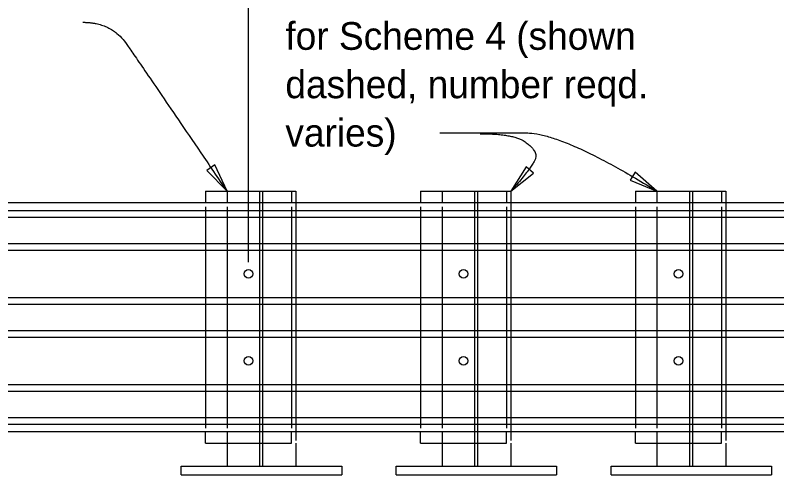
# Model space of a CAD drawing. Extents: x 21587 to 21656.3, y 56114 to 56157.2.
# Drawn here: x 21593.9 to 21599.43, y 56134.8 to 56138.14 of the extents above; entities that cross this region are included whole.
import ezdxf

# ---------------------------------------------------------------- set-up
doc = ezdxf.new("R2010")
doc.units = 0
for name, color, linetype in [('Border', 7, 'Continuous'), ('Patterning', 7, 'Continuous'), ('PlotBorder_dp', 7, 'Continuous'), ('TextMisc', 7, 'Continuous')]:
    doc.layers.add(name, color=color, linetype=linetype)

msp = doc.modelspace()

# ---------------------------------------------------------------- linework, layer by layer
at = {"layer": 'Border'}
for p, q in [((21595.4377, 56136.8635), (21595.9377, 56136.8635)), ((21595.4377, 56136.8635), (21595.4377, 56136.7802)), ((21599.7592, 56136.7801), (21587.6633, 56136.7801)), ((21587.6633, 56136.7246), (21599.7592, 56136.7246)), ((21587.6633, 56136.6764), (21599.7592, 56136.6764)), ((21587.6633, 56136.4835), (21599.7592, 56136.4835)), ((21587.6633, 56136.4353), (21599.7592, 56136.4353)), ((21587.6633, 56136.0914), (21599.7592, 56136.0914)), ((21587.6633, 56136.0431), (21599.7592, 56136.0431)), ((21587.6633, 56135.8503), (21599.7592, 56135.8503)), ((21587.6633, 56135.8022), (21599.7592, 56135.8022)), ((21587.6633, 56135.4582), (21599.7592, 56135.4582)), ((21587.6633, 56135.41), (21599.7592, 56135.41)), ((21587.6633, 56135.2172), (21599.7592, 56135.2172)), ((21587.6633, 56135.169), (21599.7592, 56135.169)), ((21599.7592, 56135.1134), (21587.6633, 56135.1134)), ((21595.4377, 56135.1135), (21595.4377, 56134.8635)), ((21595.9377, 56135.0302), (21595.9377, 56134.8635)), ((21595.1043, 56134.8635), (21596.271, 56134.8635)), ((21595.1043, 56134.801), (21595.1043, 56134.8635)), ((21595.4377, 56134.8635), (21595.9377, 56134.8635)), ((21596.271, 56134.8635), (21596.271, 56134.801)), ((21595.1043, 56134.801), (21596.271, 56134.801))]:
    msp.add_line(p, q, dxfattribs=at)
for centre in [(21595.5939, 56136.2634), (21595.5939, 56135.6303)]:
    msp.add_circle(centre, 0.0312, dxfattribs=at)
at = {"layer": 'Patterning'}
for p, q in [((21595.6772, 56134.8635), (21595.6772, 56136.8635)), ((21595.6981, 56134.8635), (21595.6981, 56136.8635)), ((21595.9377, 56136.8635), (21595.9377, 56135.0505)), ((21597.0002, 56136.8635), (21597.5002, 56136.8635)), ((21597.0002, 56136.8635), (21597.0002, 56136.7802)), ((21597.2397, 56134.8635), (21597.2397, 56136.8635)), ((21597.2606, 56134.8635), (21597.2606, 56136.8635)), ((21597.5002, 56136.8635), (21597.5002, 56135.0505)), ((21598.5627, 56136.8635), (21599.0627, 56136.8635)), ((21598.5627, 56136.8635), (21598.5627, 56136.7802)), ((21598.8022, 56134.8635), (21598.8022, 56136.8635)), ((21598.8231, 56134.8635), (21598.8231, 56136.8635)), ((21599.0627, 56136.8635), (21599.0627, 56135.0505)), ((21595.4377, 56136.7516), (21595.4377, 56135.1398)), ((21597.0002, 56136.7516), (21597.0002, 56135.1398)), ((21598.5627, 56136.7516), (21598.5627, 56135.1398)), ((21597.0002, 56135.1135), (21597.0002, 56134.8635)), ((21598.5627, 56135.1135), (21598.5627, 56134.8635)), ((21597.5002, 56135.0302), (21597.5002, 56134.8635)), ((21599.0627, 56135.0302), (21599.0627, 56134.8635)), ((21596.6668, 56134.8635), (21597.8335, 56134.8635)), ((21596.6668, 56134.801), (21596.6668, 56134.8635)), ((21597.0002, 56134.8635), (21597.5002, 56134.8635)), ((21597.8335, 56134.8635), (21597.8335, 56134.801)), ((21598.2293, 56134.8635), (21599.396, 56134.8635)), ((21598.2293, 56134.801), (21598.2293, 56134.8635)), ((21598.5627, 56134.8635), (21599.0627, 56134.8635)), ((21599.396, 56134.8635), (21599.396, 56134.801)), ((21596.6668, 56134.801), (21597.8335, 56134.801)), ((21598.2293, 56134.801), (21599.396, 56134.801))]:
    msp.add_line(p, q, dxfattribs=at)
for centre in [(21597.1564, 56136.2634), (21598.7189, 56136.2634), (21597.1564, 56135.6303), (21598.7189, 56135.6303)]:
    msp.add_circle(centre, 0.0312, dxfattribs=at)
at = {"layer": 'PlotBorder_dp'}
msp.add_line((21595.5939, 56136.3484), (21595.5939, 56141.1869), dxfattribs=at)
for points in [[(21595.4377, 56136.8635), (21595.3498, 56137.0556), (21595.2914, 56137.0159)], [(21597.5002, 56136.8635), (21597.6651, 56136.9955), (21597.6124, 56137.0424)], [(21598.5627, 56136.8635), (21598.4043, 56137.0033), (21598.3671, 56136.9433)]]:
    msp.add_lwpolyline(points, close=True, dxfattribs=at)
for points in [[(21594.3905, 56138.0929), (21594.5975, 56138.0929), (21594.8131, 56137.7824), (21595.4377, 56136.8635)], [(21596.9845, 56137.2886), (21597.3381, 56137.2886), (21597.8772, 56137.2886), (21598.5627, 56136.8635)], [(21597.2787, 56137.2823), (21597.5193, 56137.2823), (21597.6831, 56137.1678), (21597.6831, 56137.0687), (21597.5002, 56136.8635)]]:
    msp.add_open_spline(points, degree=2, dxfattribs=at)
at = {"layer": 'TextMisc'}
for p, q in [((21595.2814, 56136.8635), (21595.9064, 56136.8635)), ((21595.2814, 56136.8635), (21595.2814, 56136.7802)), ((21595.9064, 56136.8635), (21595.9064, 56136.7802)), ((21596.8439, 56136.8635), (21597.4689, 56136.8635)), ((21596.8439, 56136.8635), (21596.8439, 56136.7802)), ((21597.4689, 56136.8635), (21597.4689, 56136.7802)), ((21598.4064, 56136.8635), (21599.0314, 56136.8635)), ((21598.4064, 56136.8635), (21598.4064, 56136.7802)), ((21599.0314, 56136.8635), (21599.0314, 56136.7802)), ((21595.2814, 56136.7516), (21595.2814, 56135.1398)), ((21595.9064, 56136.7516), (21595.9064, 56135.1398)), ((21596.8439, 56136.7516), (21596.8439, 56135.1398)), ((21597.4689, 56136.7516), (21597.4689, 56135.1398)), ((21598.4064, 56136.7516), (21598.4064, 56135.1398)), ((21599.0314, 56136.7516), (21599.0314, 56135.1398)), ((21595.2814, 56135.0302), (21595.2814, 56135.1135)), ((21595.9064, 56135.0302), (21595.9064, 56135.1135)), ((21596.8439, 56135.0302), (21596.8439, 56135.1135)), ((21597.4689, 56135.0302), (21597.4689, 56135.1135)), ((21598.4064, 56135.0302), (21598.4064, 56135.1135)), ((21599.0314, 56135.0302), (21599.0314, 56135.1135)), ((21595.2814, 56135.0302), (21595.9064, 56135.0302)), ((21596.8439, 56135.0302), (21597.4689, 56135.0302)), ((21598.4064, 56135.0302), (21599.0314, 56135.0302))]:
    msp.add_line(p, q, dxfattribs=at)

# ---------------------------------------------------------------- texts
at = {"layer": 'PlotBorder_dp'}
for s, p in [('for Scheme 4 (shown ', (21595.8616, 56137.8927)), ('dashed, number reqd. ', (21595.8616, 56137.5407)), ('varies)', (21595.8616, 56137.1887))]:
    msp.add_text(s, height=0.2016, dxfattribs=at).set_placement(p)

doc.saveas('drawing.dxf')
